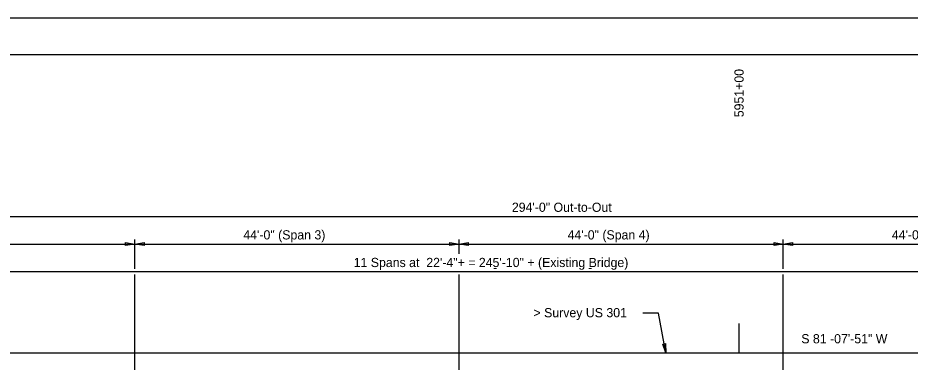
# Model space of a CAD drawing. Extents: x -10371 to -10009, y 1939 to 2167.
# Drawn here: x -10258.8 to -10137.7, y 2112.7 to 2159.5 of the extents above; entities that cross this region are included whole.
import ezdxf

# ---------------------------------------------------------------- set-up
doc = ezdxf.new("R2010")
doc.units = 0
for name, color, linetype in [('BR_AUTO DIMENSION', 7, 'Continuous'), ('BR_BORDER LINES', 7, 'Continuous'), ('BR_CENTER LINES', 7, 'Continuous'), ('BR_TEXT', 7, 'Continuous'), ('RD_SHT_IplotShp', 7, 'Continuous')]:
    doc.layers.add(name, color=color, linetype=linetype)

msp = doc.modelspace()

# ---------------------------------------------------------------- linework, layer by layer
at = {"layer": 'BR_AUTO DIMENSION'}
for p, q in [((-10330.91, 2132.54), (-10036.91, 2132.54)), ((-10350.91, 2128.79), (-10016.91, 2128.79)), ((-10330.91, 2125.04), (-10036.91, 2125.04)), ((-10171.85, 2119.41), (-10173.97, 2119.41)), ((-10170.87, 2113.99), (-10171.85, 2119.41))]:
    msp.add_line(p, q, dxfattribs=at)
for points in [[(-10244.16, 2128.98), (-10242.91, 2128.79), (-10244.16, 2128.6)], [(-10241.66, 2128.6), (-10242.91, 2128.79), (-10241.66, 2128.98)], [(-10200.16, 2128.98), (-10198.91, 2128.79), (-10200.16, 2128.6)], [(-10197.66, 2128.6), (-10198.91, 2128.79), (-10197.66, 2128.98)], [(-10156.16, 2128.98), (-10154.91, 2128.79), (-10156.16, 2128.6)], [(-10153.66, 2128.6), (-10154.91, 2128.79), (-10153.66, 2128.98)], [(-10170.9, 2115.26), (-10170.87, 2113.99), (-10171.27, 2115.19)]]:
    msp.add_lwpolyline(points, close=True, dxfattribs=at)
at = {"layer": 'BR_BORDER LINES'}
for p, q in [((-10370.58, 2159.51), (-10010.58, 2159.51)), ((-10015.58, 2154.49), (-10352.25, 2154.49))]:
    msp.add_line(p, q, dxfattribs=at)
at = {"layer": 'BR_CENTER LINES'}
for p, q in [((-10242.91, 2125.41), (-10242.91, 2129.41)), ((-10198.91, 2127.46), (-10198.91, 2129.41)), ((-10154.91, 2125.41), (-10154.91, 2129.41)), ((-10242.91, 2060.87), (-10242.91, 2124.66)), ((-10198.91, 2060.87), (-10198.91, 2124.66)), ((-10154.91, 2060.87), (-10154.91, 2124.66)), ((-10160.91, 2113.99), (-10160.91, 2117.99)), ((-10352.25, 2113.99), (-10015.58, 2113.99))]:
    msp.add_line(p, q, dxfattribs=at)
at = {"layer": 'RD_SHT_IplotShp'}
msp.add_lwpolyline([(-10370.58, 2159.49), (-10010.58, 2159.49), (-10010.58, 1939.49), (-10370.58, 1939.49)], close=True, dxfattribs=at)

# ---------------------------------------------------------------- texts
at = {"layer": 'BR_AUTO DIMENSION'}
for s, p in [('294\'-0" Out-to-Out', (-10191.74, 2133.16)), ('44\'-0" (Span 3)', (-10228.18, 2129.41)), ('44\'-0" (Span 4)', (-10184.18, 2129.41)), ('44\'-0" (Span 5)', (-10140.18, 2129.41)), ('11 Spans at  22\'-4"+ = 245\'-10" + (Existing Bridge)', (-10213.21, 2125.66)), ('-', (-10194.3, 2124.98)), ('-', (-10181.39, 2124.98))]:
    msp.add_text(s, height=1.25, dxfattribs=at).set_placement(p)
at = {"layer": 'BR_TEXT'}
msp.add_text('5951+00', height=1.25, rotation=90, dxfattribs=at).set_placement((-10160.29, 2146.01))
for s, p in [('> Survey US 301 ', (-10188.81, 2118.84)), ('S 81 -07\'-51" W', (-10152.47, 2115.3))]:
    msp.add_text(s, height=1.25, dxfattribs=at).set_placement(p)

doc.saveas('drawing.dxf')
